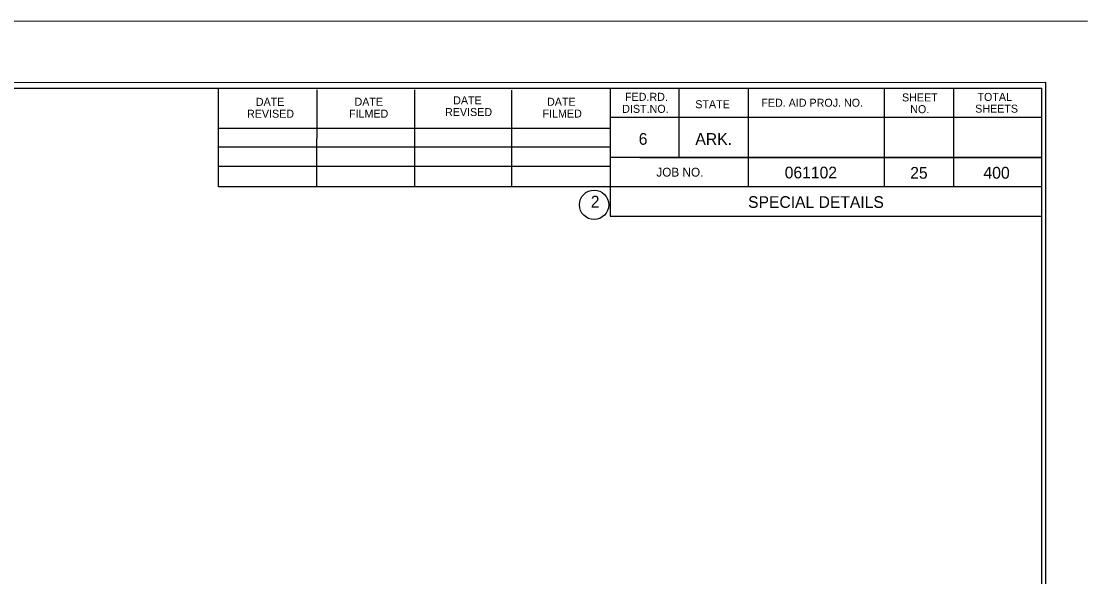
# Model space of a CAD drawing. Extents: x 714919 to 718439, y 1619644 to 1621844.
# Drawn here: x 717373 to 718439, y 1621289 to 1621844 of the extents above; entities that cross this region are included whole.
import ezdxf

# ---------------------------------------------------------------- set-up
doc = ezdxf.new("R2010")
doc.units = 0
doc.layers.add('R_Border', color=7, linetype='Continuous')
doc.layers.add('R_No Plot', color=7, linetype='Continuous')

msp = doc.modelspace()

# ---------------------------------------------------------------- linework, layer by layer
at = {"layer": 'R_Border'}
for p, q in [((718439, 1621843.8), (714919, 1621843.5)), ((715231.3, 1621777.1), (718393.1, 1621777.1)), ((717570.4, 1621678.3), (717570.5, 1621777.2)), ((717668.9, 1621678.3), (717669.1, 1621775.2)), ((717766.6, 1621678.2), (717766.6, 1621775.2)), ((717863.5, 1621678.3), (717863.5, 1621775.1)), ((717961.8, 1621777.1), (717962, 1621649.1)), ((718030.5, 1621777), (718030.4, 1621707.7)), ((718099.8, 1621777.1), (718099.8, 1621678.4)), ((718235.5, 1621777.2), (718235.5, 1621678.5)), ((718305, 1621777.3), (718305, 1621678.3)), ((718393.2, 1619722.5), (718393.1, 1621777.1)), ((718393.1, 1621747.9), (718393.1, 1621747.9)), ((718393, 1621747.5), (717962.1, 1621747.6)), ((717570.3, 1621736.9), (717961.9, 1621736.9)), ((717570.4, 1621718.3), (717961.9, 1621718.3)), ((718393.1, 1621707.7), (717962, 1621707.7)), ((717991.6, 1621707.7), (718393.1, 1621707.7)), ((717570.4, 1621678.3), (717570.4, 1621699)), ((717570.4, 1621699), (717962.1, 1621699)), ((718393.1, 1621678.3), (717570.4, 1621678.3)), ((717962, 1621649.1), (718393.1, 1621649.2))]:
    msp.add_line(p, q, dxfattribs=at)
msp.add_circle((717945.8, 1621660.4), 14.7, dxfattribs=at)
at = {"layer": 'R_No Plot'}
msp.add_lwpolyline([(715227.2, 1619717.3), (718397.1, 1619717.4), (718397.2, 1621782.5), (715227.1, 1621782.3)], close=True, dxfattribs=at)

# ---------------------------------------------------------------- texts
at = {"layer": 'R_Border'}
for s, height, rotation, p in [('FED.RD.', 8, 0.0017, (717976.7, 1621764.3)), ('SHEET', 8, 0.0017, (718253.5, 1621763.7)), ('TOTAL', 8, 0.0017, (718328.9, 1621764.2)), ('DATE', 8, 0.0017, (717607.8, 1621759.3)), ('DATE', 8, 0.0017, (717706.4, 1621759.4)), ('DATE', 8, 0.0017, (717805, 1621760.8)), ('DATE', 8, 0.0017, (717898.8, 1621759.4)), ('DIST.NO.', 8, 0.0017, (717973.9, 1621752.3)), ('STATE', 8, 0.0017, (718046.9, 1621756.9)), ('FED. AID PROJ. NO.', 8, 0.0017, (718112.9, 1621758.4)), ('NO.', 8, 0.0017, (718261.7, 1621752)), ('SHEETS', 8, 0.0017, (718326.6, 1621752.5)), ('REVISED', 8, 0.0017, (717599, 1621747.4)), ('FILMED', 8, 0.0017, (717700.9, 1621747.5)), ('REVISED', 8, 0.0017, (717796.9, 1621749.1)), ('FILMED', 8, 0.0017, (717894.3, 1621747.6)), ('6', 11.7, 0.0017, (717990.4, 1621720.4)), ('ARK.', 11.72, 0.0017, (718047, 1621720.3)), ('JOB NO.', 8.79, 0.0017, (718008, 1621688.6)), ('061102', 11.7, 0.0018, (718136.3, 1621686.8)), ('25', 11.7, 0.0018, (718261.7, 1621686.5)), ('400', 11.79, 0.0018, (718334.8, 1621686.5)), ('2', 11.7, 0.0017, (717942.5, 1621657.7)), ('SPECIAL DETAILS', 11.7, 0.0018, (718099.7, 1621657.3))]:
    msp.add_text(s, height=height, rotation=rotation, dxfattribs=at).set_placement(p)

doc.saveas('drawing.dxf')
